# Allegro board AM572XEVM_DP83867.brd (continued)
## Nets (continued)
GND: BAT1.2(-) C2.2 C3.2 C4.2 C5.1 C6.2 C8.2 C9.2 C10.2 C12.2 C13.2 C14.2 C15.2 C16.1 C17.1 C18.1 C19.1 C20.1 C21.1 C22.1 C23.2 C24.1 C25.1 C26.1 C27.1 C28.1 C29.1 C30.2 C31.2 C32.2 C33.2 C34.2 C35.2 C36.2 C37.2 C38.2 C39.2 C40.2 C41.2 C42.2 C43.2 C44.2 C45.2 C46.2 C47.2 C48.2 C49.2 C50.2 C51.2 C52.1 C53.2 C54.2 C55.1 C56.1 C57.2 C58.1 C59.2 C60.1 C61.2 C62.1 C63.2 C64.2 C65.2 C66.1 C67.1 C68.2 C69.2 C70.2 C71.1 C72.1 C73.2 C74.2 C75.2 C76.2 C77.2 C78.1 C79.2 C80.2 C81.2 C82.2 C83.2 C84.2 C85.2 C86.2 C87.2 C88.1 C89.1 C90.2 C91.2 C92.1 C93.2 C94.2 C95.1 C96.1 C97.2 C98.1 C99.2 C104.2 C105.2 C108.2 C109.2 C110.2 C111.2 C112.2 C113.2 C114.2 C115.2 C116.2 C117.2 C118.2 C119.2 C120.2 C121.2 C122.2 C123.2 C124.2 C125.2 C126.2 C127.2 C128.2 C129.2 C130.2 C131.2 C132.2 C133.2 C134.2 C135.2 C136.2 C137.2 C138.2 C139.2 C140.2 C141.1 C142.2 C143.1 C144.2 C145.1 C146.2 C147.1 C148.2 C149.1 C150.2 C151.1 C152.2 C153.1 C154.2 C155.1 C156.2 C157.2 C158.2 C159.2 C160.2 C161.2 C162.2 C163.2 C164.2 C165.2 C166.2 C167.2 C168.2 C169.2 C170.2 C171.2 C172.2 C173.2 C174.2 C175.2 C176.2 C177.2 C178.2 C179.2 C180.2 C181.2 C182.2 C183.2 C184.2 C185.2 C186.2 C187.2 C188.2 C189.2 C190.2 C191.2 C192.2 C193.2 C194.2 C195.2 C196.2 C197.2 C198.2 C199.2 C200.2 C201.2 C202.2 C203.2 C204.2 C215.1 C216.1 C217.1 C218.1 C230.1 C231.1 C232.1 C233.1 C235.2 C236.2 C237.2 C238.2 C240.2 C243.2 C245.2 C246.2 C252.2 C253.2 C254.2 C257.2 C258.2 C259.2 C260.2 C261.2 C262.2 C263.1 C264.2 C265.2 C266.2 C267.1 C268.2 C269.2 C270.1 C271.2 C272.1 C273.2 C274.1 C275.2 C276.2 C279.2 C280.2 C283.2 C284.2 C285.2 C286.2 C287.2 C288.2 C289.2 C290.1 C291.2 C292.2 C293.2 C294.2 C295.2 C300.2 C301.2 C302.2 C303.2 C304.2 C305.2 C306.2 C307.2 C308.2 C309.2 C310.2 C311.2 C312.2 C315.2 C316.2 C317.1 C318.1 C319.2 C320.2 C321.2 C322.2 C323.2 C324.2 C325.2 C326.2 C327.2 C335.2 C336.2 C337.2 C338.2 C339.2 C340.2 C341.2 C344.2 C345.2 C346.2 C347.2 C348.2 C349.2 C350.2 C354.2 C355.2 C356.2 C357.2 C359.2 C360.2 C361.2 C363.2 C364.2 C365.2 C366.2 C367.2 C368.2 C369.2 C373.2 C374.2 C375.2 C376.2 C377.2 C378.2 C381.2 C382.2 C383.2 C384.2 C385.2 C386.2 C387.2 C389.2 C390.2 C391.2 C392.2 C393.2 C394.2 C395.2 C396.2 C397.2 C398.2 C399.2 C400.2 C402.2 C403.2 C404.2 C405.2 C406.2 C407.2 C408.2 C409.1 C410.2 C411.2 C412.2 C413.2 C414.2 C415.1 C419.2 C421.2 C428.2 C429.2 C430.2 C431.2 C432.2 C433.2 C434.2 C435.2 C436.2 C437.2 C438.2 C439.2 C440.2 C441.1 C442.2 C443.2 C445.2 C452.2 C453.2 C470.2 C471.2 C472.1 C473.1 C474.1 C475.1 C478.2 C479.2 C481.2 C482.2 C483.2 C484.2 C485.2 C486.2 C487.2 C488.2 C489.2 C490.2 C491.2 C492.2 C493.2 C494.2 C495.2 C496.2 C497.2 C498.2 C499.2 C500.1 C501.2 C510.2 C511.2 C512.2 C518.2 C519.2 C520.2 C522.2 C526.2 C527.2 C529.1 C530.1 C531.1 C532.1 C533.1 C534.1 C535.1 C536.1 C537.1 C538.1 C539.1 C540.1 C541.1 C542.1 C543.1 C544.1 C547.2 C549.2 C550.2 C551.2 C555.2 C556.2 C560.2 C561.2 C562.2 C563.2 C564.2 C565.2 C566.2 C567.2 C568.2 C569.2 C570.2 C571.2 C572.2 C573.2 C574.2 C575.2 C576.2 C577.2 C578.2 C579.2 C580.2 C583.2 C584.2 C585.2 C586.2 C587.2 C588.2 C589.2 C590.2 C591.2 C592.2 C593.2 D1.2(ANODE) D2.2(ANODE) D3.1(C) D12.2(G) D13.2(G) D14.2(G) D15.2(G) D16.2(G) D17.2(G) D18.2(G) D19.2(G) D20.4(GND) D21.4(GND) D22.4(GND) D23.4(GND) D24.2(ANODE) D25.3(GND) D26.3(GND) D27.3(GND) D28.3(GND) D29.3(GND) D30.3(GND) D31.3(GND) D32.3(GND) D33.3(GND) D34.2(GND) D35.2(GND) D36.2(GND) D37.2(GND) D38.3(GND) D40.3(GND) D41.1(C) D42.2(GND) FB9.1 J1.2 J3.3 J4.3 J6.1 L10.2 L11.2 L12.2 L21.2 L22.2 L24.2 MH5.1(TP) P1.2 P1.SHLD1 P1.SHLD2 P1.SHLD3 P1.SHLD4 P2.6 P3.6 P4.4(TDIS) P4.8(GND.1) P4.10(GND.2) P4.12(GND.3) P4.16(GND.4) P4.20(GND.5) P5.1(GND) P5.20(1_GND) P6.4(GND1) P6.5(GND2) P6.8(GND3) P6.11(GND4) P7.5(G1) P10.1 P11.2(D2 SHIELD) P11.5(D1 SHIELD) P11.8(D0 SHIELD) P11.11(CK SHIELD) P11.17(GND) P12.6(VSS) P12.10(CD2) P12.11(G1) P12.12(G2) P12.13(G3) P12.14(G4) P13.4(GND) P13.7(GNDD) P15.4(GND0) P15.7(GNDD0) P15.13(GND1) P15.16(GNDD1) P16.1 P16.2 P16.28 P16.30 P16.31 P16.32 P16.58 P16.60 P16.A2 P17.1 P17.2 P17.31 P17.32 P17.A2 P18.1 P18.2 P18.31 P18.32 P18.A2 P19.1 P19.4 P19.5 P19.9 P19.10 P19.13 P19.16 P19.19 P19.22 P19.23 P19.26 P19.29 P19.31 P19.32 P19.34 P19.37 P19.38 P19.41 P19.44 P19.47 P19.50 P19.51 P19.54 P19.57 P19.60 P19.A2 Q3.1(4) Q3.4 Q4.1(4) Q4.4 Q5.2(SOURCE) Q6.2(SOURCE) Q7.2(S) R5.1 R6.2 R11.2 R12.2 R14.1 R21.2 R22.2 R24.2 R26.2 R27.2 R28.1 R43.2 R47.2 R49.2 R50.2 R51.2 R54.1 R58.2 R66.2 R68.2 R69.1 R97.2 R98.1 R180.2 R181.2 R183.2 R188.2 R190.2 R191.2 R192.2 R193.2 R194.2 R195.2 R200.1 R203.2 R205.2 R206.1 R207.1 R209.1 R219.2 R220.2 R221.2 R222.2 R231.2 R232.2 R236.2 R244.2 R274.2 R275.2 R276.2 R277.2 R278.2 R287.1 R293.1 R296.1 R297.2 R298.2 R299.1 R300.1 R311.2 R312.2 R319.1 R323.1 R328.2 R329.1 R331.1 R332.1 R333.2 R334.2 R384.2 R385.1 R386.1 R387.1 R395.2 R397.2 R400.1 R401.1 R402.1 R403.1 R404.2 R410.2 R411.2 R416.2 R417.2 R421.2 R422.2 R432.2 R434.2 R440.1 R441.1 R478.1 S1.1(A) S2.1(A) U1.7(GND) U1.9(PAD) U2.5(GND) U2.9(PWR_PAD) U3.7(GND) U3.9(PAD) U4.2(GND) U4.4(ADD0) U5.A1(SUB_GND_A1) U5.A4(REFGND1) U5.A7(GNDANA) U5.A13(SUB_GND_A13) U5.B2(GPADC_IN0) U5.B8(SYNC_TO_EXCLOCK) U5.B10(SUB_GND_B10) U5.B11(SUB_GND_B11) U5.C2(GPADC_IN1) U5.C3(GPADC_IN2) U5.C12(SMPS12_FBK_GND) U5.D4(SMPS7_GND_1) U5.D5(SMPS7_GND_2) U5.D6(SUB_GND_D6) U5.D7(SUB_GND_D7) U5.D10(SMPS1_GND_1) U5.E4(SMPS7_GND_3) U5.E7(VAC/ACOK) U5.E8(SUB_GND_E8) U5.E9(SMPS1_GND_2) U5.E10(SMPS1_GND_3) U5.F4(SMPS4_GND_1) U5.F5(AGND.1) U5.F6(SUB_GND_F6) U5.F7(SUB_GND_F7) U5.F9(SMPS2_GND_1) U5.F10(SMPS2_GND_2) U5.G4(SMPS4_GND_2) U5.G5(SMPS4_GND_3) U5.G7(SUB_GND_G7) U5.G10(SMPS2_GND_3) U5.H4(SMPS5_GND_1) U5.H5(SMPS5_GND_2) U5.H6(SUB_GND_H6) U5.H7(SUB_GND_H7) U5.H10(SMPS3_GND_1) U5.J4(SMPS5_GND_3) U5.J6(SUB_GND_J6) U5.J9(SMPS3_GND_2) U5.J10(SMPS3_GND_3) U5.K3(SMPS45_FDBK_GND) U5.L5(SMPS6_GND) U5.L6(SMPS6_GND_1) U5.L7(SMPS9_GND) U5.L8(SMPS9_GND_1) U5.L9(SMPS8_GND_1) U5.L10(SMPS8_GND) U5.M1(SUB_GND_M1) U5.M2(SUB_GND_M2) U5.M12(GND_DIG) U5.M13(AGND.2) U5.N1(SUB_GND_N1) U5.N2(VIO_GND) U5.N13(SUB_GND_N13) U6.4(VSS) U7.14(GND.1) U7.22(GND.2) U7.33(PWR_PAD) U8.1(A0) U8.2(A1) U8.3(NC) U8.4(VSS) U9.2(GND) U10.3(GND) U11.A1(VSS.9) U11.A2(VSS.11) U11.A6(VSS.15) U11.A14(VSS.41) U11.A23(VSS.68) U11.A28(VSS.79) U11.AA8(VSS.17) U11.AA9(VSS.19) U11.AA10(VSS.14) U11.AA11(VSSA_USB.2) U11.AA14(VSS.48) U11.AA15(VSS.51) U11.AA20(VSS.61) U11.AB11(VSSA_USB.1) U11.AB14(VSS.40) U11.AB20(VSS.60) U11.AD1(VSS.3) U11.AD10(VSSA_USB3) U11.AD13(VSSA_PCIE.1) U11.AD19(VSSA_HDMI.2) U11.AD24(VSS.70) U11.AE10(VSSA_SATA) U11.AE13(VSSA_PCIE.2) U11.AE19(VSSA_HDMI.1) U11.AG1(VSS.2) U11.AH1(VSS.1) U11.AH2(VSS.10) U11.AH8(VSS.53) U11.AH20(VSS.52) U11.AH28(VSS.75) U11.B1(VSS.8) U11.D13(VSS.39) U11.D19(VSS.59) U11.E13(VSS.38) U11.E19(VSS.58) U11.F1(VSS.7) U11.F7(VSS.54) U11.G7(VSS.57) U11.G8(VSS.65) U11.G9(VSS.66) U11.H12(VSS.33) U11.J12(VSS.32) U11.J15(VSS.XX) U11.J28(VSS.78) U11.K1(VSS.6) U11.K4(VSS.12) U11.K5(VSS.13) U11.K15(VSS.28) U11.K24(VSS.55) U11.K25(VSS.56) U11.L13(VSS.37) U11.L14(VSS.46) U11.M19(VSS.69) U11.N14(VSS.X5) U11.N15(VSS.16) U11.N19(VSS.18) U11.N24(VSS.72) U11.N25(VSS.74) U11.P28(VSS.77) U11.R1(VSS.5) U11.R12(VSS.29) U11.R13(VSS.X6) U11.R15(VSS.43) U11.R21(VSS.64) U11.T10(VSS.21) U11.T11(VSS.26) U11.T12(VSS.23) U11.T14(VSS.X7) U11.T15(VSS.42) U11.T17(VSS.47) U11.T18(VSS.24) U11.T21(VSS.27) U11.U14(VSSA_VIDEO) U11.U15(VSS.X8) U11.U17(VSS.X9) U11.U20(VSS.62) U11.U21(VSS.63) U11.V15(VSS.30) U11.V17(VSS.X10) U11.W1(VSS.4) U11.W15(VSS.36) U11.W24(VSS.71) U11.W25(VSS.73) U11.W28(VSS.76) U12.2(GND) U13.2(GND) U14.49(GND) U15.49(GND) U16.6(GND) U16.11(PAD) U17.65(PAD) U18.6(DVSS) U18.21(DRVSS) U19.2(GND) U19.3(ENN) U20.1(1\O\E\) U20.4(GND) U21.5(GND1) U21.13(GND2) U21.18(GND3) U22.C4(VSSQ4) U22.E7(VSS2) U22.G5(VSS1) U22.H10(VSS3) U22.K8(VSS4) U22.N2(VSSQ1) U22.N5(VSS5) U22.P4(VSSQ3) U22.P6(VSSQ2) U23.A9(VSS.1) U23.B1(VSSQ.1) U23.B3(VSS.2) U23.B9(VSSQ.2) U23.D1(VSSQ.3) U23.D8(VSSQ.4) U23.E1(VSS.3) U23.E2(VSSQ.5) U23.E8(VSSQ.6) U23.F9(VSSQ.7) U23.G1(VSSQ.8) U23.G8(VSS.4) U23.G9(VSSQ.9) U23.J2(VSSDL) U23.J8(VSS.5) U23.M1(VSS.6) U23.M9(VSS.7) U23.P1(VSS.8) U23.P9(VSS.9) U23.T1(VSS.10) U23.T9(VSS.11) U24.A9(VSS.1) U24.B1(VSSQ.1) U24.B3(VSS.2) U24.B9(VSSQ.2) U24.D1(VSSQ.3) U24.D8(VSSQ.4) U24.E1(VSS.3) U24.E2(VSSQ.5) U24.E8(VSSQ.6) U24.F9(VSSQ.7) U24.G1(VSSQ.8) U24.G8(VSS.4) U24.G9(VSSQ.9) U24.J2(VSSDL) U24.J8(VSS.5) U24.M1(VSS.6) U24.M9(VSS.7) U24.P1(VSS.8) U24.P9(VSS.9) U24.T1(VSS.10) U24.T9(VSS.11) U25.A9(VSS.1) U25.B1(VSSQ.1) U25.B3(VSS.2) U25.B9(VSSQ.2) U25.D1(VSSQ.3) U25.D8(VSSQ.4) U25.E1(VSS.3) U25.E2(VSSQ.5) U25.E8(VSSQ.6) U25.F9(VSSQ.7) U25.G1(VSSQ.8) U25.G8(VSS.4) U25.G9(VSSQ.9) U25.J2(VSSDL) U25.J8(VSS.5) U25.M1(VSS.6) U25.M9(VSS.7) U25.P1(VSS.8) U25.P9(VSS.9) U25.T1(VSS.10) U25.T9(VSS.11) U26.A9(VSS.1) U26.B1(VSSQ.1) U26.B3(VSS.2) U26.B9(VSSQ.2) U26.D1(VSSQ.3) U26.D8(VSSQ.4) U26.E1(VSS.3) U26.E2(VSSQ.5) U26.E8(VSSQ.6) U26.F9(VSSQ.7) U26.G1(VSSQ.8) U26.G8(VSS.4) U26.G9(VSSQ.9) U26.J2(VSSDL) U26.J8(VSS.5) U26.M1(VSS.6) U26.M9(VSS.7) U26.P1(VSS.8) U26.P9(VSS.9) U26.T1(VSS.10) U26.T9(VSS.11) U27.4(PGND) U27.8(GND) U27.11(PWRPAD) U28.7(GND) U28.9(PAD) U29.1(GND) U29.11(PAD) U30.1(GND) U30.11(PAD) U31.1(GND1) U31.10(GND2) U31.12(GND3) U31.14(GND4) U31.20(GND5) U31.25(GND6) U31.27(GND7) U32.5(GND1) U32.6(GND3) U32.7(GND2) U32.8(GND4) U33.3(GND1) U33.13(GND3) U33.17(GND5) U33.18(GND4) U33.19(GND2) U33.21(PAD) U34.4(GND) U42.1(NC) U42.3(GND) U44.3(GND) U47.3(GND#3) U47.8(GND#8) U48.3(GND#3) U48.8(GND#8) U49.3(GND#3) U49.8(GND#8) U50.3(GND#3) U50.8(GND#8) U51.3(GND) Y8.1 Y8.2(NC0) Y8.4(NC1) Y9.2(NC0) Y9.4(NC1)
GND_EARTH: C215.2 C216.2 C230.2 C231.2 C415.2 C419.1 C441.2 C472.2 C473.2 C474.2 C475.2 D8.1 D9.1 D10.1 D11.1 MH1.1(TP) MH2.1(TP) MH3.1(TP) MH4.1(TP) P5.SHLD1 P5.SHLD2 P5.SHLD3 P5.SHLD4 P6.14(S1) P6.15(S2) P6.16(S3) P6.17(S4) P7.S1(G2) P7.S2(G3) P7.S3(G4) P7.S4(G5) P11.MTG1 P11.MTG2 P11.MTG3 P11.MTG4 P13.10(SHLD0) P13.11(SHLD1) P15.19(SHLD0) P15.20(SHLD1) P15.21(SHLD2) P15.22(SHLD3) R299.2 R300.2 R331.2 R332.2 R384.1 R385.2 R386.2 R387.2 R400.2 R401.2 R402.2 R403.2 S1.3(B) S1.4(BB) S2.3(B) S2.4(BB)
GND_SIGNAL: C247.2 C248.2 C249.2 FB9.2 P8.1 P9.1 R226.2 R228.2 R234.2 R235.2 U18.17(AVSS_ADC) U18.26(AVSS_DAC) U18.33(PAD)
VBUS_DET: R413.2 R414.2 U11.B11(GPIO4_21)
VCC_SENSE: R30.2 U5.B3(VCC_SENSE)
VCC_SENSE2: R29.2 U5.A11(VCC_SENSE2)
VDD_1.1: C481.1 C482.1 C483.1 C484.1 C485.1 C486.1 C487.1 C488.1 C489.1 R201.1 U16.9(OUTB) U16.10(OUTA) U17.5(VDD1) U17.8(VDD2) U17.13(VDD3) U17.21(VDD4) U17.28(VDD5) U17.31(VDD6) U17.51(VDD7) U17.57(VDD8)
VDD_1V0: C583.1 L25.2 R471.1 R473.1 TP28.1 U5.J8(SMPS9_FBK)
VDD_1V8: C47.1 C185.1 C186.1 C187.1 C188.1 C189.1 C190.1 C191.1 C192.1 C193.1 C194.1 C195.1 C196.1 L9.2 Q8.3(COLLECTOR) Q9.3(COLLECTOR) R302.2 R420.2 R425.2 TP19.1 U5.L11(SMPS8_FDBK) U11.AA7(VDDS_MLBP.1) U11.AA18(VDDS18V_DDR1.1) U11.AA19(VDDS18V_DDR1.2) U11.G18(VDDS18V.8) U11.H17(VDDS18V.11) U11.J21(VDDS18V_DDR2.3) U11.J22(VDDS18V_DDR2.4) U11.M8(VDDS18V.9) U11.M9(VDDS18V.7) U11.N8(VDDS18V.4) U11.N21(VDDS18V_DDR2.2) U11.P8(VDDS18V.5) U11.P20(VDDS18V_DDR2.5) U11.P21(VDDS18V_DDR2.1) U11.R8(VDDS18V.3) U11.T8(VDDS18V.2) U11.V21(VDDS18V.12) U11.V22(VDDS18V.6) U11.W17(VDDS18V.10) U11.W18(VDDS18V.1) U11.W21(VDDS18V_DDR1.4) U11.Y7(VDDS_MLBP.2) U11.Y21(VDDS18V_DDR1.3) U35.3(ANODE) U43.3(ANODE)
VDD_2V5: C584.1 L26.2 R472.1 R475.1 TP29.1 U5.B1(SMPS7_FDBK)
VDD_3V3: C15.1 C30.1 C50.1 C81.1 C113.1 C114.1 C115.1 C116.1 C117.1 C118.1 C119.1 C120.1 C121.1 C122.1 C123.1 C124.1 C125.1 C126.1 C127.1 C128.1 C129.1 C130.1 C131.1 C132.1 C133.1 C134.1 C135.1 C136.1 C137.1 C138.1 C139.1 C263.2 C268.1 C269.1 C271.1 C272.2 C389.1 C470.1 C471.1 C490.1 C491.1 C492.1 C493.1 C494.1 C501.1 C585.1 J3.1 J4.1 J6.3 L12.1 L22.1 L23.1 P4.5(TVD) P12.4(VDD) P16.A3 P17.A3 P18.A3 P19.A3 Q8.2(EMITTER) R8.1 R15.1 R16.1 R17.1 R18.2 R19.2 R32.1 R33.1 R37.2 R38.2 R45.1 R46.1 R48.1 R59.1 R62.1 R189.2 R196.2 R197.2 R204.2 R212.1 R213.1 R237.1 R243.1 R245.1 R246.1 R247.1 R248.1 R249.2 R286.1 R288.2 R294.1 R309.1 R310.1 R313.2 R321.1 R391.1 R392.1 R398.1 R399.1 R408.1 R415.1 R418.1 R419.1 R437.1 R470.1 R474.1 R476.1 U2.7(VOUT.2) U2.8(VOUT.1) U4.5(V+) U5.D9(VIO_IN) U6.8(VCC) U8.8(VCC) U11.AB6(VDDSHV7.1) U11.AB7(VDDSHV7.2) U11.AD5(VDDSHV6.2) U11.AD7(VDDSHV6.4) U11.AE7(VDDSHV6.3) U11.AF5(VDDSHV6.1) U11.B6(VDDSHV2.1) U11.B23(VDDSHV3.9) U11.C24(VDDSHV4.1) U11.D10(VDDSHV2.5) U11.D16(VDDSHV3.4) U11.D22(VDDSHV3.8) U11.E3(VDDSHV1.1) U11.E5(VDDSHV1.4) U11.E10(VDDSHV2.4) U11.E16(VDDSHV3.3) U11.E22(VDDSHV3.7) U11.G4(VDDSHV1.2) U11.G5(VDDSHV1.3) U11.G15(VDDSHV3.2) U11.H8(VDDSHV1.5) U11.H9(VDDSHV1.6) U11.H10(VDDSHV2.2) U11.H11(VDDSHV2.3) U11.H15(VDDSHV3.1) U11.H16(VDDSHV3.6) U11.H18(VDDSHV3.5) U11.H19(VDDSHV3.10) U11.J8(VDDSHV11.2) U11.K8(VDDSHV11.1) U11.N4(VDDSHV10.2) U11.N5(VDDSHV10.4) U11.P10(VDDSHV10.6) U11.R7(VDDSHV10.5) U11.R10(VDDSHV10.7) U11.T4(VDDSHV10.1) U11.T5(VDDSHV10.3) U11.U10(VDDSHV9.3) U11.W4(VDDSHV9.1) U11.W5(VDDSHV9.2) U16.1(INA) U16.2(INB) U16.4(BIAS) U16.5(EN) U17.16(VDD33_1) U17.34(VDD33_2) U17.52(VDD33_3) U17.63(VDD33_4) U20.7(2OE) U20.8(VCC) U21.23(VCCA) U22.C6(VCCQ4) U22.M4(VCCQ5) U22.N4(VCCQ3) U22.P5(VCCQ2) U27.10(VIN) U33.6(VCC1) U33.10(VCC4) U33.16(VCC2) U33.20(VCC3) U42.5(VCC) U44.5(VCC) U51.5(VCC)
VDD_3V3_ON: R10.2 R434.1 U2.3(ON) U5.F8(REGEN1)
VDD_3V3_SP: C94.1 C97.1 C104.1 R32.2 R41.1 R42.1 R44.1 R52.1 R405.1 U9.5(VCC) U10.5(VCC) U12.6(VDD) U34.8(VCC)
VDD_CDC: C430.1 C431.1 C433.1 L22.3 U7.1(VDD2_OUT1) U7.4(VDD1_OUT0)
VDD_CORE: C54.1 C55.2 C56.2 C58.2 C60.2 C62.2 C65.1 C66.2 C67.2 C71.2 C72.2 P3.3 R36.2 TP18.1 U5.K6(SMPS6_FBK) U11.H13(VDD.18) U11.H14(VDD.22) U11.J17(VDD.X1) U11.J18(VDD.X2) U11.L7(VDD.34) U11.L8(VDD.15) U11.N10(VDD.6) U11.N13(VDD.16) U11.P11(VDD.9) U11.P12(VDD.12) U11.P13(VDD.X3) U11.R11(VDD.8) U11.R16(VDD.26) U11.R19(VDD.27) U11.T13(VDD.13) U11.T16(VDD.25) U11.T19(VDD.X7) U11.U8(VDD.29) U11.U9(VDD.2) U11.U13(VDD.3) U11.U16(VDD.X8) U11.V8(VDD.1) U11.V16(VDD.X9)
VDD_DDR: C38.1 C156.1 C157.1 C158.1 C159.1 C160.1 C161.1 C162.1 C163.1 C164.1 C165.1 C166.1 C167.1 C168.1 C169.1 C170.1 C171.1 C172.1 C173.1 C174.1 C175.1 C176.1 C177.1 C178.1 C179.1 C180.1 C181.1 C182.1 C183.1 C184.1 C277.2 C278.2 C281.2 C282.2 C283.1 C284.1 C285.1 C286.1 C287.1 C288.1 C289.1 C290.2 C291.1 C292.1 C293.1 C294.1 C295.1 C296.2 C297.2 C298.2 C299.2 C300.1 C301.1 C302.1 C303.1 C304.1 C305.1 C306.1 C307.1 C308.1 C309.1 C310.1 C311.1 C312.1 C313.2 C314.2 C315.1 C316.1 C317.2 C318.2 C319.1 C320.1 C321.1 C322.1 C323.1 C324.1 C325.1 C326.1 C327.1 C328.2 C329.2 C330.2 C331.2 C332.2 C333.2 C334.1 C335.1 C336.1 C337.1 C338.1 C339.1 C340.1 C341.1 C342.2 C343.2 C344.1 C345.1 C346.1 C347.1 C348.1 C349.1 C350.1 C351.2 C352.2 C353.2 C354.1 C355.1 C356.1 C357.1 C358.2 C359.1 C360.1 C361.1 C362.2 C363.1 C364.1 C365.1 C366.1 C367.1 C368.1 C369.1 C370.2 C371.2 C372.2 C373.1 C374.1 C375.1 C376.1 C377.1 C378.1 C379.2 C380.2 C381.1 C382.1 C383.1 C384.1 C385.1 C386.1 C387.1 C388.1 C391.1 C392.1 C393.1 C394.1 L5.2 R273.1 R285.1 TP16.1 U5.K13(SMPS3_FDBK) U11.AA21(VDDS_DDR1.4) U11.AA22(VDDS_DDR1.2) U11.AB21(VDDS_DDR1.3) U11.AB22(VDDS_DDR1.7) U11.AB24(VDDS_DDR1.10) U11.AB25(VDDS_DDR1.11) U11.AC22(VDDS_DDR1.6) U11.AD26(VDDS_DDR1.12) U11.AG20(VDDS_DDR1.9) U11.AG28(VDDS_DDR1.5) U11.AH27(VDDS_DDR1.13) U11.E24(VDDS_DDR2.9) U11.G22(VDDS_DDR2.5) U11.G23(VDDS_DDR2.6) U11.H20(VDDS_DDR2.1) U11.H21(VDDS_DDR2.11) U11.H22(VDDS_DDR2.4) U11.J27(VDDS_DDR2.12) U11.L20(VDDS_DDR2.8) U11.L21(VDDS_DDR2.3) U11.M20(VDDS_DDR2.13) U11.M21(VDDS_DDR2.2) U11.T24(VDDS_DDR2.7) U11.T25(VDDS_DDR2.10) U11.W16(VDDS_DDR1.1) U11.W27(VDDS_DDR1.8) U23.A1(VDDQ.1) U23.A8(VDDQ.2) U23.B2(VDD.1) U23.C1(VDDQ.3) U23.C9(VDDQ.4) U23.D2(VDDQ.5) U23.D9(VDD.2) U23.E9(VDDQ.6) U23.F1(VDDQ.7) U23.G7(VDD.3) U23.H2(VDDQ.8) U23.H9(VDDQ.9) U23.K2(VDDL) U23.K8(VDD.4) U23.N1(VDD.5) U23.N9(VDD.6) U23.R1(VDD.7) U23.R9(VDD.8) U24.A1(VDDQ.1) U24.A8(VDDQ.2) U24.B2(VDD.1) U24.C1(VDDQ.3) U24.C9(VDDQ.4) U24.D2(VDDQ.5) U24.D9(VDD.2) U24.E9(VDDQ.6) U24.F1(VDDQ.7) U24.G7(VDD.3) U24.H2(VDDQ.8) U24.H9(VDDQ.9) U24.K2(VDDL) U24.K8(VDD.4) U24.N1(VDD.5) U24.N9(VDD.6) U24.R1(VDD.7) U24.R9(VDD.8) U25.A1(VDDQ.1) U25.A8(VDDQ.2) U25.B2(VDD.1) U25.C1(VDDQ.3) U25.C9(VDDQ.4) U25.D2(VDDQ.5) U25.D9(VDD.2) U25.E9(VDDQ.6) U25.F1(VDDQ.7) U25.G7(VDD.3) U25.H2(VDDQ.8) U25.H9(VDDQ.9) U25.K2(VDDL) U25.K8(VDD.4) U25.N1(VDD.5) U25.N9(VDD.6) U25.R1(VDD.7) U25.R9(VDD.8) U26.A1(VDDQ.1) U26.A8(VDDQ.2) U26.B2(VDD.1) U26.C1(VDDQ.3) U26.C9(VDDQ.4) U26.D2(VDDQ.5) U26.D9(VDD.2) U26.E9(VDDQ.6) U26.F1(VDDQ.7) U26.G7(VDD.3) U26.H2(VDDQ.8) U26.H9(VDDQ.9) U26.K2(VDDL) U26.K8(VDD.4) U26.N1(VDD.5) U26.N9(VDD.6) U26.R1(VDD.7) U26.R9(VDD.8) U27.2(VLDOIN)
VDD_DSP: C51.1 C52.2 C53.1 C57.1 C59.1 C61.1 C63.1 C64.1 C68.1 C69.1 C70.1 C73.1 C74.1 C75.1 C76.1 C78.2 C79.1 C80.1 P3.2 R35.2 TP17.1 U5.K2(SMPS45_FDBK) U11.J13(VDD_DSP.7) U11.K10(VDD_DSP.8) U11.K11(VDD_DSP.9) U11.K12(VDD_DSP.10) U11.K13(VDD_DSP.11) U11.L10(VDD_DSP.2) U11.L11(VDD_DSP.4) U11.L12(VDD_DSP.12) U11.M10(VDD_DSP.1) U11.M11(VDD_DSP.5) U11.M12(VDD_DSP.3) U11.M13(VDD_DSP.6) U11.U11(VDD_GPU.5) U11.U12(VDD_GPU.6) U11.U18(VDD_IVA.1[ECO]) U11.U19(VDD_IVA.2[ECO]) U11.V10(VDD_GPU.2) U11.V11(VDD_GPU.3) U11.V14(VDD_GPU.7) U11.V18(VDD_IVA.3[ECO]) U11.V19(VDD_IVA.4[ECO]) U11.W10(VDD_GPU.1) U11.W11(VDD_GPU.4) U11.W13(VDD_GPU.8)
VDD_MPU: C77.1 C82.1 C83.1 C84.1 C85.1 C86.1 C87.1 C88.2 C89.2 C90.1 C91.1 C92.2 C93.1 P3.5 R34.2 R54.2 TP13.1 U5.B13(SMPS12_FBK) U11.K17(VDD_MPU.10) U11.K18(VDD_MPU.2) U11.L15(VDD_MPU.11) U11.L16(VDD_MPU.12) U11.L17(VDD_MPU.6) U11.L18(VDD_MPU.8) U11.L19(VDD_MPU.3) U11.M15(VDD_MPU.13) U11.M16(VDD_MPU.14) U11.M17(VDD_MPU.5) U11.M18(VDD_MPU.7) U11.N17(VDD_MPU.4) U11.N18(VDD_MPU.1) U11.P17(VDD_MPU.15) U11.P18(VDD_MPU.9) U11.R18(VDD_MPU.16) U12.5(SENSE1)
VDD_RTC: C28.2 C108.1 U5.A5(LDO9_OUT) U11.AB15(VDD_RTC)
VDD_SD: C21.2 C140.1 D20.1(VCC) D21.1(VCC) D22.1(VCC) D23.1(VCC) R260.1 R261.1 R262.1 R263.1 R264.1 R265.1 R272.1 U5.C6(LDO1_OUT) U11.W8(VDDSHV8.2) U11.Y8(VDDSHV8.1)
VDD_SHV5: C22.2 C105.1 Q9.2(EMITTER) R423.1 R424.1 U5.B6(LDO2_OUT) U11.V12(VDDSHV5)
VDDA_1V8_PHYA: C24.2 C243.1 C245.1 L11.3 U5.K11(LDO3_OUT) U11.AA13(VDDA_USB1) U11.AB12(VDDA_USB2)
VDDA_1V8_PHYB: C500.2 L24.3 U5.K12(LDO4_OUT)
VDDA_1V8_PLL: C29.2 C99.1 L10.1 U5.B5(LDOLN_OUT) U11.AD16(VDDA_OSC.1) U11.AE16(VDDA_OSC.2)
VIN3A_CLKO: P16.50 U11.P1(VIN3X_CLKO)
VIN3A_D0: P16.51 R239.1 U11.M6(VIN3A_D0)
VIN3A_D1: P16.52 R189.1 U11.M2(VIN3A_D1)
VIN3A_D2: P16.16 R183.1 U11.L5(VIN3A_D2)
VIN3A_D3: P16.22 R188.1 U11.M1(VIN3A_D3)
VIN3A_D4: P16.15 R182.1 U11.L6(VIN3A_D4)
VIN3A_D5: P16.18 R187.1 U11.L4(VIN3A_D5)
VIN3A_D6: P16.53 R181.1 U11.L3(VIN3A_D6)
VIN3A_D7: P16.54 R180.1 U11.L2(VIN3A_D7)
VIN3A_D8: P16.23 R196.1 U11.L1(VIN3A_D8)
VIN3A_D9: P16.57 R195.1 U11.K2(VIN3A_D9)
VIN3A_D10: P16.56 R194.1 U11.J1(VIN3A_D10)
VIN3A_D11: P16.55 R193.1 U11.J2(VIN3A_D11)
VIN3A_D12: P16.24 R192.1 U11.H1(VIN3A_D12)
VIN3A_D13: P16.26 R191.1 U11.J3(VIN3A_D13)
VIN3A_D14: P16.27 R190.1 U11.H2(VIN3A_D14)
VIN3A_D15: P16.25 R197.1 R432.1 U11.H3(VIN3A_D15)
VIN3A_D16: P16.36 U11.R6(VIN3A_D16)
VIN3A_D17: P16.43 U11.T9(VIN3A_D17)
VIN3A_D18: P16.12 U11.T6(VIN3A_D18)
VIN3A_D19: P16.42 U11.T7(VIN3A_D19)
VIN3A_D20: P16.10 U11.P6(VIN3A_D20)
VIN3A_D21: P16.13 U11.R9(VIN3A_D21)
VIN3A_D22: P16.6 U11.R5(VIN3A_D22)
VIN3A_D23: P16.45 U11.P5(VIN3A_D23)
VIN3A_DEO: P16.14 U11.N9(VIN3A_DEO)
VIN3A_FLD: P16.44 U11.P9(VIN3A_FLD)
VIN3A_HSYNC: P16.9 U11.N7(VIN3A_HSYNC)
VIN3A_VSYNC: P16.37 U11.R4(VIN3A_VSYNC)
VSSA_OSC0: C100.2 C101.2 R244.1 U11.AF15(VSSA_OSC0)
VSSA_OSC1: C102.2 C103.2 R395.1 U11.AC14(VSSA_OSC1) Y3.2(NC0) Y3.4(NC1)
74801SS: R200.2 U16.7(SS)
AIC_AVDD_DAC3.3: C248.1 C249.1 L13.2 U18.25(AVDD_DAC)
AIC_BCLK: R227.2 R231.1 U18.2(BCLK)
AIC_BCLKR: R227.1 U11.B18(MCASP3_ACLKX)
AIC_DIN: R225.2 R232.1 U18.4(DIN)
AIC_DINR: R225.1 U11.B19(MCASP3_AXR0)
AIC_DOUT: R229.2 U18.5(DOUT)
AIC_DOUTR: R229.1 U11.C17(MCASP3_AXR1)
AIC_DRVDD3.3: C257.1 C258.1 C259.1 L15.2 U18.18(DRVDD#18) U18.24(DRVDD#24)
AIC_DVDD: C261.1 C262.1 U18.32(DVDD) U19.5(OUT)
AIC_IOVDD3.3: C253.1 C254.1 L14.2 U18.7(IOVDD)
AIC_MCLK: R223.2 U18.1(MCLK)
AIC_MCLKR: R223.1 U11.D18(CLKOOUT2)
AIC_WCLK: R224.2 U18.3(WCLK)
AIC_WCLKR: R224.1 U11.F15(MCASP3_FSX)
AM_CAP0: C141.2 U11.Y15(CAP_VDDRAM_CORE3)
AM_CAP1: C143.2 U11.J19(CAP_VDDRAM_CORE2)
AM_CAP2: C145.2 U11.P19(CAP_VDDRAM_CORE4)
AM_CAP3: C147.2 U11.Y16(CAP_VDDRAM_CORE5)
AM_CAP4: C149.2 U11.K9(CAP_VBBLDO_DSP)
AM_CAP5: C151.2 U11.J9(CAP_VDDRAM_DSP2)
AM_CAP6: C153.2 U11.K19(CAP_VDDRAM_MPU2)
AM_CAP7: C155.2 U11.L9(CAP_VDDRAM_CORE1)
AM_CAP8: C142.1 U11.R20(CAP_VBBLDO_IVA)
AM_CAP9: C144.1 U11.Y14(CAP_VBBLDO_GPU)
AM_CAP10: C146.1 U11.J16(CAP_VBBLDO_MPU)
AM_CAP11: C148.1 U11.J10(CAP_VDDRAM_DSP)
AM_CAP12: C150.1 U11.T20(CAP_VDDRAM_IVA)
AM_CAP13: C152.1 U11.Y13(CAP_VDDRAM_GPU)
AM_CAP14: C154.1 R417.1 U11.K16(CAP_VDDRAM_MPU1)
AUDIN_L: R230.1 U18.14(IN2L)
AUDIN_R: R233.1 U18.16(IN2R)
AUDIN_RL: C256.1 R233.2
AUDIN_RR: C255.1 R230.2
AUDIO_L: C250.1 U18.27(LEFT_LOP)
AUDIO_R: C251.1 U18.29(RIGHT_LOP)
AUXFAN_EN: R24.1 U5.A12(GPIO_2/REGEN2) U32.1(EN)
B_UART3_RX: P10.4 R236.1 U20.2(1A)
B_UART3_TX: P10.5 U20.3(2Y)
BATEN0: R204.1 U17.36(PWRON1Z_BATEN1) U29.4(EN1)
BATEN1: U17.35(PWRON2Z_BATEN2) U29.5(EN2)
BATEN2: U17.33(PWRON3Z_BATEN3) U30.4(EN1)
BATEN3: U17.32(PWRON4Z_BATEN4) U30.5(EN2)
BU_BATT: BAT1.1(+) R416.1 U6.3(VBAT)
CDC_CAP1: C436.1 U7.19(REG_CAP1)
CDC_CAP2: C437.1 U7.17(REG_CAP2)
CDC_OE: R313.1 U7.7(OE)
CDC_OS1: R310.2 R312.1 U7.10(OS1)
CDC_OS2: R309.2 R311.1 U7.11(OS0)
CDC_OSCIN: C435.1 U7.21(XIN) Y8.3
CLKOUT3: P17.41 U11.C23(CLKOUT3)
CON.PCIE_RXN0: P19.25 U11.AG13(PCIE_RXN0)
CON.PCIE_RXN1: P19.18 U11.AG11(PCIE_RXN1)
CON.PCIE_RXP0: P19.24 U11.AH13(PCIE_RXP0)
CON.PCIE_RXP1: P19.17 U11.AH11(PCIE_RXP1)
CON.PCIE_TXN0: C423.2 P19.28
CON.PCIE_TXN1: C425.2 P19.21
CON.PCIE_TXP0: C422.2 P19.27
CON.PCIE_TXP1: C424.2 P19.20
CON_MMC1_CLK: D21.3(IO1) P12.5(CLOCK) R262.2 R269.2
CON_MMC1_CMD: D21.5(IO2) P12.3(CMD) R263.2 R267.2
CON_MMC1_DAT0: D20.5(IO2) P12.7(DAT0) R261.2 R270.2
CON_MMC1_DAT1: D20.3(IO1) P12.8(DAT1) R260.2 R271.2
CON_MMC1_DAT2: D22.5(IO2) P12.1(DAT2) R265.2 R266.2
CON_MMC1_DAT3: D22.3(IO1) P12.2(CD/DAT3) R264.2 R268.2
CONN_SATA_RXN: C418.2 U33.12(RX2N)
CONN_SATA_RXP: C420.2 U33.11(RX2P)
CONN_SATA_TXN: C417.2 U33.14(TX1N)
CONN_SATA_TXP: C416.1 U33.15(TX1P)
CPU_NMIN: R46.2 R47.1 U11.D21(NMIN)
CPU_POR_RESETN: R41.2 R53.2 U9.6(C)
CPU_RESETN: R42.2 R55.1 U10.1(B)
DCAN1_RX: P17.20 U11.G19(DCAN1_RX)
DCAN1_TX: P17.50 U11.G20(DCAN1_TX)
DDR1_A0: R364.1 U11.AD20(DDR1_A0) U23.N3(A0) U24.N3(A0)
DDR1_A1: R365.1 U11.AC19(DDR1_A1) U23.P7(A1) U24.P7(A1)
DDR1_A2: R371.1 U11.AC20(DDR1_A2) U23.P3(A2) U24.P3(A2)
DDR1_A3: R376.1 U11.AB19(DDR1_A3) U23.N2(A3) U24.N2(A3)
DDR1_A4: R366.1 U11.AF21(DDR1_A4) U23.P8(A4) U24.P8(A4)
DDR1_A5: R367.1 U11.AH22(DDR1_A5) U23.P2(A5) U24.P2(A5)
DDR1_A6: R381.1 U11.AG23(DDR1_A6) U23.R8(A6) U24.R8(A6)
DDR1_A7: R369.1 U11.AE21(DDR1_A7) U23.R2(A7) U24.R2(A7)
DDR1_A8: R383.1 U11.AF22(DDR1_A8) U23.T8(A8) U24.T8(A8)
DDR1_A9: R368.1 U11.AE22(DDR1_A9) U23.R3(A9) U24.R3(A9)
DDR1_A10: R373.1 U11.AD21(DDR1_A10) U23.L7(A10) U24.L7(A10)
DDR1_A11: R380.1 U11.AD22(DDR1_A11) U23.R7(A11) U24.R7(A11)
DDR1_A12: R379.1 U11.AC21(DDR1_A12) U23.N7(A12) U24.N7(A12)
DDR1_A13: R370.1 U11.AF18(DDR1_A13) U23.T3(A13) U24.T3(A13)
DDR1_A14: R382.1 U11.AE17(DDR1_A14) U23.T7(A14) U24.T7(A14)
DDR1_A15: R375.1 U11.AD18(DDR1_A15) U23.M7(NC.M7/A15) U24.M7(NC.M7/A15)
DDR1_BA0: R363.1 U11.AF17(DDR1_BA0) U23.M2(BA0) U24.M2(BA0)
DDR1_BA1: R377.1 U11.AE18(DDR1_BA1) U23.N8(BA1) U24.N8(BA1)
DDR1_BA2: R378.1 U11.AB18(DDR1_BA2) U23.M3(BA2) U24.M3(BA2)
DDR1_CASN: R361.1 U11.AC18(DDR1_CASN) U23.K3(CAS#) U24.K3(CAS#)
DDR1_CKE: R282.1 R333.1 U11.AG22(DDR1_CKE) U23.K9(CKE) U24.K9(CKE)
DDR1_CLK0: R284.1 U11.AG24(DDR1_CK) U23.J7(CK) U24.J7(CK)
DDR1_CLK0N: R283.1 U11.AH24(DDR1_NCK) U23.K7(CK#) U24.K7(CK#)
DDR1_CLK_TERM: C388.2 R283.2 R284.2
DDR1_CSN0: R362.1 U11.AH23(DDR1_CS0N) U23.L2(CS#) U24.L2(CS#)
DDR1_D0: U11.AF25(DDR1_D0) U23.E3(DQ0)
DDR1_D1: U11.AF26(DDR1_D1) U23.H3(DQ4)
DDR1_D2: U11.AG26(DDR1_D2) U23.F8(DQ3)
DDR1_D3: U11.AH26(DDR1_D3) U23.F7(DQ1)
DDR1_D4: U11.AF24(DDR1_D4) U23.G2(DQ6)
DDR1_D5: U11.AE24(DDR1_D5) U23.H7(DQ7)
DDR1_D6: U11.AF23(DDR1_D6) U23.F2(DQ2)
DDR1_D7: U11.AE23(DDR1_D7) U23.H8(DQ5)
DDR1_D8: U11.AC23(DDR1_D8) U23.D7(DQ8)
DDR1_D9: U11.AF27(DDR1_D9) U23.C3(DQ9)
DDR1_D10: U11.AG27(DDR1_D10) U23.A3(DQ15)
DDR1_D11: U11.AF28(DDR1_D11) U23.C8(DQ10)
DDR1_D12: U11.AE26(DDR1_D12) U23.B8(DQ14)
DDR1_D13: U11.AC25(DDR1_D13) U23.A2(DQ13)
DDR1_D14: U11.AC24(DDR1_D14) U23.C2(DQ11)
DDR1_D15: U11.AD25(DDR1_D15) U23.A7(DQ12)
DDR1_D16: U11.V20(DDR1_D16) U24.E3(DQ0)
DDR1_D17: U11.W20(DDR1_D17) U24.H8(DQ5)
DDR1_D18: U11.AB28(DDR1_D18) U24.F8(DQ3)
DDR1_D19: U11.AC28(DDR1_D19) U24.H7(DQ7)
DDR1_D20: U11.AC27(DDR1_D20) U24.H3(DQ4)
DDR1_D21: U11.Y19(DDR1_D21) U24.G2(DQ6)
DDR1_D22: U11.AB27(DDR1_D22) U24.F7(DQ1)
DDR1_D23: U11.Y20(DDR1_D23) U24.F2(DQ2)
DDR1_D24: U11.AA23(DDR1_D24) U24.D7(DQ8)
DDR1_D25: U11.Y22(DDR1_D25) U24.C3(DQ9)
DDR1_D26: U11.Y23(DDR1_D26) U24.A3(DQ15)
DDR1_D27: U11.AA24(DDR1_D27) U24.B8(DQ14)
DDR1_D28: U11.Y24(DDR1_D28) U24.A7(DQ12)
DDR1_D29: U11.AA26(DDR1_D29) U24.C8(DQ10)
DDR1_D30: U11.AA25(DDR1_D30) U24.A2(DQ13)
DDR1_D31: U11.AA28(DDR1_D31) U24.C2(DQ11)
DDR1_DQM0: U11.AD23(DDR1_DQM0) U23.E7(LDM)
DDR1_DQM1: U11.AB23(DDR1_DQM1) U23.D3(UDM)
DDR1_DQM2: U11.AC26(DDR1_DQM2) U24.E7(LDM)
DDR1_DQM3: U11.AA27(DDR1_DQM3) U24.D3(UDM)
DDR1_DQS0: U11.AH25(DDR1_DQS0) U23.F3(LDQS)
DDR1_DQS1: U11.AE27(DDR1_DQS1) U23.C7(UDQS)
DDR1_DQS2: U11.AD27(DDR1_DQS2) U24.F3(LDQS)
DDR1_DQS3: U11.Y28(DDR1_DQS3) U24.C7(UDQS)
DDR1_DQS_ECC: R274.1 U11.V27(DDR1_DQS_ECC)
DDR1_DQSN0: U11.AG25(DDR1_DQSN0) U23.G3(LDQS#)
DDR1_DQSN1: U11.AE28(DDR1_DQSN1) U23.B7(UDQS#)
DDR1_DQSN2: U11.AD28(DDR1_DQSN2) U24.G3(LDQS#)
DDR1_DQSN3: U11.Y27(DDR1_DQSN3) U24.B7(UDQS#)
DDR1_DQSN_ECC: R273.2 U11.V28(DDR1_DQSN_ECC)
DDR1_ODT0: R360.1 U11.AE20(DDR1_ODT0) U23.K1(ODT) U24.K1(ODT)
DDR1_RASN: R372.1 U11.AF20(DDR1_RASN) U23.J3(RAS#) U24.J3(RAS#)
DDR1_RST: TP20.1 U11.AG21(DDR1_RST) U23.T2(RSTN) U24.T2(RSTN)
DDR1_WEN: R374.1 U11.AH21(DDR1_WEN) U23.L3(WE#) U24.L3(WE#)
DDR2_A0: R355.1 U11.R25(DDR2_A0) U25.N3(A0) U26.N3(A0)
DDR2_A1: R356.1 U11.R26(DDR2_A1) U25.P7(A1) U26.P7(A1)
DDR2_A2: R346.1 U11.R28(DDR2_A2) U25.P3(A2) U26.P3(A2)
DDR2_A3: R344.1 U11.R27(DDR2_A3) U25.N2(A3) U26.N2(A3)
DDR2_A4: R347.1 U11.P23(DDR2_A4) U25.P8(A4) U26.P8(A4)
DDR2_A5: R345.1 U11.P22(DDR2_A5) U25.P2(A5) U26.P2(A5)
DDR2_A6: R338.1 U11.P25(DDR2_A6) U25.R8(A6) U26.R8(A6)
DDR2_A7: R358.1 U11.N20(DDR2_A7) U25.R2(A7) U26.R2(A7)
DDR2_A8: R359.1 U11.P27(DDR2_A8) U25.T8(A8) U26.T8(A8)
DDR2_A9: R336.1 U11.N27(DDR2_A9) U25.R3(A9) U26.R3(A9)
DDR2_A10: R340.1 U11.N23(DDR2_A10) U25.L7(A10) U26.L7(A10)
DDR2_A11: R337.1 U11.P26(DDR2_A11) U25.R7(A11) U26.R7(A11)
DDR2_A12: R354.1 U11.N28(DDR2_A12) U25.N7(A12) U26.N7(A12)
DDR2_A13: R357.1 U11.T22(DDR2_A13) U25.T3(A13) U26.T3(A13)
DDR2_A14: R339.1 U11.R22(DDR2_A14) U25.T7(A14) U26.T7(A14)
DDR2_A15: R342.1 U11.U22(DDR2_A15) U25.M7(NC.M7/A15) U26.M7(NC.M7/A15)
DDR2_BA0: R350.1 U11.U23(DDR2_BA0) U25.M2(BA0) U26.M2(BA0)
DDR2_BA1: R353.1 U11.U27(DDR2_BA1) U25.N8(BA1) U26.N8(BA1)
DDR2_BA2: R352.1 U11.U26(DDR2_BA2) U25.M3(BA2) U26.M3(BA2)
DDR2_CASN: R349.1 U11.U28(DDR2_CASN) U25.K3(CAS#) U26.K3(CAS#)
DDR2_CKE: R334.1 R348.1 U11.U24(DDR2_CKE) U25.K9(CKE) U26.K9(CKE)
DDR2_CLK0: R281.1 U11.T28(DDR2_CK) U25.J7(CK) U26.J7(CK)
DDR2_CLK0N: R280.1 U11.T27(DDR2_NCK) U25.K7(CK#) U26.K7(CK#)
DDR2_CLK_TRM: C334.2 R280.2 R281.2
DDR2_CSN0: R351.1 U11.P24(DDR2_CSN0) U25.L2(CS#) U26.L2(CS#)
DDR2_D0: U11.E26(DDR2_D0) U25.D7(DQ8)
DDR2_D1: U11.G25(DDR2_D1) U25.C2(DQ11)
DDR2_D2: U11.F25(DDR2_D2) U25.A3(DQ15)
DDR2_D3: U11.F24(DDR2_D3) U25.B8(DQ14)
DDR2_D4: U11.F26(DDR2_D4) U25.A2(DQ13)
DDR2_D5: U11.F27(DDR2_D5) U25.C3(DQ9)
DDR2_D6: U11.E27(DDR2_D6) U25.A7(DQ12)
DDR2_D7: U11.E28(DDR2_D7) U25.C8(DQ10)
DDR2_D8: U11.H23(DDR2_D8) U25.E3(DQ0)
DDR2_D9: U11.H25(DDR2_D9) U25.H3(DQ4)
DDR2_D10: U11.H24(DDR2_D10) U25.H8(DQ5)
DDR2_D11: U11.H26(DDR2_D11) U25.G2(DQ6)
DDR2_D12: U11.G26(DDR2_D12) U25.H7(DQ7)
DDR2_D13: U11.J25(DDR2_D13) U25.F2(DQ2)
DDR2_D14: U11.J26(DDR2_D14) U25.F8(DQ3)
DDR2_D15: U11.J24(DDR2_D15) U25.F7(DQ1)
DDR2_D16: U11.L22(DDR2_D16) U26.D7(DQ8)
DDR2_D17: U11.K20(DDR2_D17) U26.C8(DQ10)
DDR2_D18: U11.K21(DDR2_D18) U26.A2(DQ13)
DDR2_D19: U11.L23(DDR2_D19) U26.C2(DQ11)
DDR2_D20: U11.L24(DDR2_D20) U26.C3(DQ9)
DDR2_D21: U11.J23(DDR2_D21) U26.B8(DQ14)
DDR2_D22: U11.K22(DDR2_D22) U26.A3(DQ15)
DDR2_D23: U11.J20(DDR2_D23) U26.A7(DQ12)
DDR2_D24: U11.L27(DDR2_D24) U26.E3(DQ0)
DDR2_D25: U11.L26(DDR2_D25) U26.H8(DQ5)
DDR2_D26: U11.L25(DDR2_D26) U26.H7(DQ7)
DDR2_D27: U11.L28(DDR2_D27) U26.F7(DQ1)
DDR2_D28: U11.M23(DDR2_D28) U26.F8(DQ3)
DDR2_D29: U11.M24(DDR2_D29) U26.H3(DQ4)
DDR2_D30: U11.M25(DDR2_D30) U26.F2(DQ2)
DDR2_D31: U11.M26(DDR2_D31) U26.G2(DQ6)
DDR2_DQM0: U11.F28(DDR2_DQM0) U25.D3(UDM)
DDR2_DQM1: U11.G24(DDR2_DQM1) U25.E7(LDM)
DDR2_DQM2: U11.K23(DDR2_DQM2) U26.D3(UDM)
DDR2_DQM3: U11.M22(DDR2_DQM3) U26.E7(LDM)
DDR2_DQS0: U11.G28(DDR2_DQS0) U25.C7(UDQS)
DDR2_DQS1: U11.H27(DDR2_DQS1) U25.F3(LDQS)
DDR2_DQS2: U11.K27(DDR2_DQS2) U26.C7(UDQS)
DDR2_DQS3: U11.M28(DDR2_DQS3) U26.F3(LDQS)
DDR2_DQSN0: U11.G27(DDR2_DQSN0) U25.B7(UDQS#)
DDR2_DQSN1: U11.H28(DDR2_DQSN1) U25.G3(LDQS#)
DDR2_DQSN2: U11.K28(DDR2_DQSN2) U26.B7(UDQS#)
DDR2_DQSN3: U11.M27(DDR2_DQSN3) U26.G3(LDQS#)
DDR2_ODT0: R341.1 U11.R23(DDR2_ODT0) U25.K1(ODT) U26.K1(ODT)
DDR2_RASN: R279.1 U11.T23(DDR2_RASN) U25.J3(RAS#) U26.J3(RAS#)
DDR2_RST: TP21.1 U11.R24(DDR2_RST) U25.T2(RSTN) U26.T2(RSTN)
DDR2_WEN: R343.1 U11.U25(DDR2_WEN) U25.L3(WE#) U26.L3(WE#)
DDR_REFIN: C390.1 R285.2 R287.2 U27.1(REFIN)
DDR_VREF_OFFN: Q5.1(GATE) R288.1 U11.A22(GPIO7_11) U27.7(EN)
DDR_VREFSTL1: C273.1 C275.1 C276.1 C277.1 C278.1 R290.2 U11.Y18(DDR1_VREF0) U23.H1(VREFDQ) U23.M8(VREFCA) U24.H1(VREFDQ) U24.M8(VREFCA)
DDR_VREFSTL2: C274.2 C279.1 C280.1 C281.1 C282.1 R291.2 U11.N22(DDR2_VREF0) U25.H1(VREFDQ) U25.M8(VREFCA) U26.H1(VREFDQ) U26.M8(VREFCA)
DMA_EVT1: P16.35 U11.P7(DMA_EVT1)
DMA_EVT3: P16.11 U11.N6(DMA_EVT3)
DMA_EVT4: P16.17 U11.M4(DMA_EVT4)
EEWP: R37.1 TP4.1(TP) U8.7(WP)
EHRPWM2_TRIPZONE_INPUT: P18.6 U11.F6(EHRPWM2_TRIPZONE_INPUT)
EHRPWM2A: P17.5 U11.AC5(EHRPWM2A)
EHRPWM2B: P18.44 U11.D3(EHRPWM2B)
EMAC[0]_RXC: U11.U5(EMAC(0)_RXC) U14.32(RX_CLK)
EMAC[0]_RXCTL: U11.V5(EMAC(0)_RXCTL) U14.38(RX_DV/RX_CTRL)
EMAC[0]_RXD0: U11.W2(EMAC(0)_RXD0) U14.33(RX_D0)
EMAC[0]_RXD1: U11.Y2(EMAC(0)_RXD1) U14.34(RX_D1)
EMAC[0]_RXD2: U11.V3(EMAC(0)_RXD2) U14.35(RX_D2)
EMAC[0]_RXD3: U11.V4(EMAC(0)_RXD3) U14.36(RX_D3)
EMAC[0]_TXC: R85.1 U11.W9(EMAC(0)_TXC)
EMAC[0]_TXCTL: R84.1 U11.V9(EMAC(0)_TXCTL)
EMAC[0]_TXD0: R86.1 U11.U6(EMAC(0)_TXD0)
EMAC[0]_TXD1: R87.1 U11.V6(EMAC(0)_TXD1)
EMAC[0]_TXD2: R88.1 U11.U7(EMAC(0)_TXD2)
EMAC[0]_TXD3: R89.1 U11.V7(EMAC(0)_TXD3)
EMAC[1]_RXC: U11.C5(EMAC(1)_RXC) U15.32(RX_CLK)
EMAC[1]_RXCTL: U11.A3(EMAC(1)_RXCTL) U15.38(RX_DV/RX_CTRL)
EMAC[1]_RXD0: R461.2 U11.A4(EMAC(1)_RXD0) U15.33(RX_D0)
EMAC[1]_RXD1: U11.B5(EMAC(1)_RXD1) U15.34(RX_D1)
EMAC[1]_RXD2: U11.B4(EMAC(1)_RXD2) U15.35(RX_D2)
EMAC[1]_RXD3: U11.B3(EMAC(1)_RXD3) U15.36(RX_D3)
EMAC[1]_TXC: R112.1 U11.D5(EMAC(1)_TXC)
EMAC[1]_TXCTL: R111.1 U11.C2(EMAC(1)_TXCTL)
EMAC[1]_TXD0: R113.1 U11.D6(EMAC(1)_TXD0)
EMAC[1]_TXD1: R114.1 U11.B2(EMAC(1)_TXD1)
EMAC[1]_TXD2: R115.1 U11.C4(EMAC(1)_TXD2)
EMAC[1]_TXD3: R118.1 U11.C3(EMAC(1)_TXD3)
EMMC_VDD1.1: C270.2 U22.C2(VCCI)
EMU0: P4.13(EMU0) R59.2 U11.G21(EMU0)
EMU1: P4.14(EMU1) R62.2 U11.D24(EMU1)
EMU_RSTN: P4.15(SRST) R44.2 U10.2(A)
ENET0_INTN: R468.2 U11.D26(GPIO7_27) U14.44(INT/PWDN)
ENET1_INTN: R469.2 U11.D28(GPIO7_26) U15.44(INT/PWDN)
ENET_PORZ: R39.2 R40.2 U44.2(B) U51.2(B)
ESATA_R+: C420.1 P6.10(B+)
ESATA_R-: C418.1 P6.9(B-)
ESATA_T+: C416.2 P6.6(A+)
ESATA_T-: C417.1 P6.7(A-)
ETH0_1V0: C518.1 C519.1 C520.1 C522.1 C566.1 C567.1 C568.1 C569.1 R471.2 U14.6(VDD1P0#6) U14.24(VDD1P0#24) U14.31(VDD1P0#31) U14.42(VDD1P0#42)
ETH0_2V5: C526.1 C527.1 C570.1 C571.1 R472.2 U14.3(VDDA2P5#3) U14.9(VDDA2P5#9)
ETH0_3V3: C510.1 C511.1 C512.1 C563.1 C564.1 C565.1 R442.1 R468.1 R470.2 U14.19(VDDIO#19) U14.30(VDDIO#30) U14.41(VDDIO#41)
ETH0_LED0_YEL_LINK: P5.27(LED1_A) U14.47(LED_0)
ETH0_LED2_GRN_ACTIV: P5.29(LED2_A) U14.45(LED_2)
ETH0_RBIAS: R440.2 U14.12(RBIAS)
ETH0_RESET: U14.43(RESET_N) U51.4(Y)
ETH0_TRCT[0]: C590.1 P5.14(1_TRCT1)
ETH0_TRCT[1]: C591.1 P5.22(1_TRCT2)
ETH0_TRCT[2]: C592.1 P5.17(1_TRCT3)
ETH0_TRCT[3]: C593.1 P5.25(1_TRCT4)
ETH0_TRD[0]N: C530.2 P5.21(1_TRD1_N) U14.2(TD_M_A) U47.2(D1-) U47.9(NC9)
ETH0_TRD[0]P: C529.2 P5.15(1_TRD1_P) U14.1(TD_P_A) U47.1(D1+) U47.10(NC10)
ETH0_TRD[1]N: C531.2 P5.16(1_TRD2_N) U14.5(TD_M_B) U47.5(D2-) U47.6(NC6)
ETH0_TRD[1]P: C532.2 P5.23(1_TRD2_P) U14.4(TD_P_B) U47.4(D2+) U47.7(NC7)
ETH0_TRD[2]N: C533.2 P5.24(1_TRD3_N) U14.8(TD_M_C) U48.2(D1-) U48.9(NC9)
ETH0_TRD[2]P: C534.2 P5.18(1_TRD3_P) U14.7(TD_P_C) U48.1(D1+) U48.10(NC10)
ETH0_TRD[3]N: C535.2 P5.19(1_TRD4_N) U14.11(TD_M_D) U48.5(D2-) U48.6(NC6)
ETH0_TRD[3]P: C536.2 P5.26(1_TRD4_P) U14.10(TD_P_D) U48.4(D2+) U48.7(NC7)
ETH0_XI: C217.2 U14.15(XI) Y5.2(NC0)
ETH0_XO: C218.2 R479.1 Y5.1
ETH1_1V0: C547.1 C549.1 C550.1 C551.1 C575.1 C576.1 C577.1 C578.1 R473.2 U15.6(VDD1P0#6) U15.24(VDD1P0#24) U15.31(VDD1P0#31) U15.42(VDD1P0#42)
ETH1_2V5: C555.1 C556.1 C579.1 C580.1 R475.2 U15.3(VDDA2P5#3) U15.9(VDDA2P5#9)
ETH1_3V3: C560.1 C561.1 C562.1 C572.1 C573.1 C574.1 R461.1 R469.1 R474.2 U15.19(VDDIO#19) U15.30(VDDIO#30) U15.41(VDDIO#41)
ETH1_LED0_YEL_LINK: P5.31(LED3_A) U15.47(LED_0)
ETH1_LED2_GRN_ACTIV: P5.33(LED4_A) U15.45(LED_2)
ETH1_RBIAS: R441.2 U15.12(RBIAS)
ETH1_RESET: U15.43(RESET_N) U44.4(Y)
ETH1_TRCT[0]: C586.1 P5.7(2_TRCT1)
ETH1_TRCT[1]: C587.1 P5.12(2_TRCT2)
ETH1_TRCT[2]: C588.1 P5.4(2_TRCT3)
ETH1_TRCT[3]: C589.1 P5.9(2_TRCT4)
ETH1_TRD[0]N: C537.2 P5.13(2_TRD1_N) U15.2(TD_M_A) U49.2(D1-) U49.9(NC9)
ETH1_TRD[0]P: C544.2 P5.6(2_TRD1_P) U15.1(TD_P_A) U49.1(D1+) U49.10(NC10)
ETH1_TRD[1]N: C538.2 P5.5(2_TRD2_N) U15.5(TD_M_B) U49.5(D2-) U49.6(NC6)
ETH1_TRD[1]P: C539.2 P5.11(2_TRD2_P) U15.4(TD_P_B) U49.4(D2+) U49.7(NC7)
ETH1_TRD[2]N: C540.2 P5.10(2_TRD3_N) U15.8(TD_M_C) U50.2(D1-) U50.9(NC9)
ETH1_TRD[2]P: C541.2 P5.3(2_TRD3_P) U15.7(TD_P_C) U50.1(D1+) U50.10(NC10)
ETH1_TRD[3]N: C542.2 P5.2(2_TRD4_N) U15.11(TD_M_D) U50.5(D2-) U50.6(NC6)
ETH1_TRD[3]P: C543.2 P5.8(2_TRD4_P) U15.10(TD_P_D) U50.4(D2+) U50.7(NC7)
ETH1_XI: C232.2 R451.2 U15.15(XI) Y6.2(NC0)
ETH1_XO: C233.2 R480.1 Y6.1
ETH_CLK_OUT: R451.1 R477.1
ETH_RESETN: R476.2 U11.U3(GPIO3_17) U51.1(A)
EXP_SATA_RXN: P19.7 U31.22(B1-)
EXP_SATA_RXP: P19.8 U31.21(B1+)
EXP_SATA_TXN: P19.36 U31.23(B0-)
EXP_SATA_TXP: P19.35 U31.24(B0+)
EXT_WAKE: P18.35 R33.2 R49.1 U6.7(MFP) U11.AC16(WAKEUP3)
GPIO2_2: P16.46 U11.P4(GPIO2_2)
GPIO2_3: P16.7 U11.R3(GPIO2_3)
GPIO2_4: P16.40 U11.T2(GPIO2_4)
GPIO2_5: P16.38 U11.U2(GPIO2_5)
GPIO2_6: P16.39 U11.U1(GPIO2_6)
GPIO2_8: P16.8 U11.R2(GPIO2_8)
GPIO2_17: P16.48 U11.P3(GPIO2_17)
GPIO2_19: P16.41 U11.T1(GPIO2_19)
GPIO2_20: P16.49 U11.P2(GPIO2_20)
GPIO2_23: P16.21 U11.N1(GPIO2_23)
GPIO2_24: P16.47 U11.M5(GPIO2_24)
GPIO2_25: P16.19 U11.M3(GPIO2_25)
GPIO2_28: P16.20 U11.N2(GPIO2_28)
GPIO2_31: P19.55 U11.AH7(GPIO2_31)
GPIO3_6: P19.56 U11.AG7(GPIO3_6)
GPIO3_7: P19.52 U11.AH6(GPIO3_7)
GPIO3_8: P19.45 U11.AH3(GPIO3_8)
GPIO3_9: P19.48 U11.AH5(GPIO3_9)
GPIO3_10: P19.53 U11.AG6(GPIO3_10)
GPIO3_11: P19.14 U11.AH4(GPIO3_11)
GPIO3_12: P19.15 U11.AG4(GPIO3_12)
GPIO3_14: P19.46 U11.AG3(GPIO3_14)
GPIO3_15: P19.49 U11.AG5(GPIO3_15)
GPIO3_16: P19.42 U11.AF2(GPIO3_16)
GPIO3_18: P19.43 U11.AF3(GPIO3_18)
GPIO3_20: P19.11 U11.AF1(GPIO3_20)
GPIO3_23: P19.39 U11.AE1(GPIO3_23)
GPIO3_24: P19.12 U11.AE2(GPIO3_24)
GPIO3_26: P19.40 U11.AD2(GPIO3_26)
GPIO3_28: P18.11 U11.E1(GPIO3_28)
GPIO3_29: R437.2 U11.G2(GPIO3_29) U44.1(A)
GPIO3_30: P18.36 U11.H7(GPIO3_30)
GPIO4_7: P18.43 U11.C1(GPIO4_7)
GPIO4_8: P18.39 U11.E4(GPIO4_8)
GPIO4_9: P18.38 U11.F5(GPIO4_9)
GPIO4_10: P18.7 U11.E6(GPIO4_10)
GPIO4_17: P16.3 U11.A12(GPIO4_17)
GPIO5_4: P17.47 U11.G13(GPIO5_4)
GPIO5_5: P17.17 U11.J11(GPIO5_5)
GPIO5_6: P17.45 U11.E12(GPIO5_6)
GPIO5_7: P17.15 U11.F13(GPIO5_7)
GPIO5_8: P17.55 U11.C12(GPIO5_8)
GPIO5_9: P17.25 U11.D12(GPIO5_9)
GPIO5_10: P16.34 U11.B12(GPIO5_10)
GPIO5_11: P16.4 U11.A11(GPIO5_11)
GPIO5_12: P16.33 U11.B13(GPIO5_12)
GPIO5_18: P18.59 U11.V2(UART3_RXD)
GPIO5_19: P18.29 U11.Y1(UART3_TXD)
GPIO6_11: P17.3 U11.AB4(GPIO6_11)
GPIO6_18: P17.58 U11.E17(GPIO6_18)
GPIO6_19: P17.28 U11.B26(GPIO6_19)
GPIO7_7: P17.51 U11.A25(GPIO7_7)
GRSTZ: C246.1 U17.50(GRSTZ)
HDMI1_DDC_SCL: R246.2 U11.C25(HDMI1_DDC_SCL) U21.1(SCL_A)
HDMI1_DDC_SDA: R245.2 U11.F17(HDMI1_DDC_SDA) U21.2(SDA_A)
HDMI_5VOUT: C265.1 P11.18(+5V) U21.12(5V_OUT)
HDMI_CEC_A: U11.B20(HDMI_CEC) U21.24(CEC_A)
HDMI_CEC_B: P11.13(CE REMOTE) R237.2 U21.6(CEC_B)
HDMI_CT_HPD: R248.2 U11.A24(GPIO7_10) U21.11(CT_HPD)
HDMI_HPD_A: U11.B21(HDMI_HPD) U21.3(HPD_A)
HDMI_HPD_B: P11.19(HP DET) U21.9(HPD_B)
HDMI_LS_OE: R247.2 U11.AG8(GPIO2_30) U21.4(LS_OE)
HDMI_SCL_B: P11.15(DDC CLK) R241.2 U21.7(SCL_B)
HDMI_SDA_B: P11.16(DDC DATA) R242.1 U21.8(SDA_B)
HDMI_TX0+: D16.1(I) FL3.3 P11.7(D0+)
HDMI_TX0-: D17.1(I) FL3.2 P11.9(D0-)
HDMI_TX1+: D14.1(I) FL2.3 P11.4(D1+)
HDMI_TX1-: D15.1(I) FL2.2 P11.6(D1-)
HDMI_TX2+: D12.1(I) FL1.3 P11.1(D2+)
HDMI_TX2-: D13.1(I) FL1.2 P11.3(D2-)
HDMI_TXC+: D18.1(I) FL4.3 P11.10(CK+)
HDMI_TXC-: D19.1(I) FL4.2 P11.12(CK-)
HUB_XI: C235.1 R202.1 U17.62(XI) Y7.1
HUB_XO: C240.1 R202.2 U17.61(XO) Y7.2
I2C1_SCL: R17.2 R212.2 U4.1(SCL) U5.L1(I2C1_SCL_SCK) U8.6(SCL) U11.C20(I2C1_SCL) U18.8(SCL)
I2C1_SDA: R16.2 R213.2 U4.6(SDA) U5.L2(I2C1_SDA_SDI) U8.5(SDA) U11.C21(I2C1_SDA) U18.9(SDA)
I2C3_SCL: R392.2 R393.1 U6.6(SCL) U11.D14(I2C3_SCL)
I2C3_SDA: R391.2 R394.1 U6.5(SDA) U11.C14(I2C3_SDA)
I2C4_SCL: P17.46 U11.J14(I2C4_SCL)
I2C4_SDA: P17.53 U11.B14(I2C4_SDA)
I2C5_SCL: P18.4 U11.F12(I2C5_SCL)
I2C5_SDA: P18.3 U11.G12(I2C5_SDA)
LDO_VRTC: C19.2 C110.1 J5.2 R20.2 R23.1 R56.1 R214.2 R433.2 U5.A8(LDOVRTC_OUT) U11.AB13(VDDA_RTC)
LEDAA: D4.2(A) R215.2
LEDAC: D4.1(C) Q3.6(3)
LEDBA: D5.2(A) R216.2
LEDBC: D5.1(C) Q3.3
LEDCA: D6.2(A) R217.2
LEDCC: D6.1(C) Q4.6(3)
LEDDA: D7.2(A) R218.2
LEDDC: D7.1(C) Q4.3
LEFT_IN: C255.2 D10.2 P9.2 R235.1
LEFT_OUT: C250.2 D8.2 P8.2 R226.1
MCASP2_ACLKR: P17.44 U11.E15(MCASP2_ACLKR)
MCASP2_AXR0: P17.54 U11.B15(MCASP2_AXR0)
MCASP2_AXR1: P17.23 U11.A15(MCASP2_AXR1)
MCASP2_AXR2: P17.18 U11.C15(MCASP2_AXR2)
MCASP2_AXR3: P17.22 U11.A16(MCASP2_AXR3)
MCASP2_AXR4: P17.16 U11.D15(MCASP2_AXR4)
MCASP2_AXR5: P17.24 U11.B16(MCASP2_AXR5)
MCASP2_AXR6: P17.26 U11.B17(MCASP2_AXR6)
MCASP2_AXR7: P17.56 U11.A17(MCASP2_AXR7)
MCASP2_CLKX: P17.21 U11.A19(MCASP2_ACLKX)
MCASP2_FSR: P17.57 U11.A20(MCASP2_FSR)
MCASP2_FSX: P17.52 U11.A18(MCASP2_FSX)
MCASP7_AXR0: P16.5 U11.E14(MCASP7_AXR0)
MCASP7_AXR1: P17.49 U11.A13(MCASP7_AXR1)
MCASP7_CLKX: P17.48 U11.G14(MCASP7_CLKX)
MCASP7_FSX: P17.19 U11.F14(MCASP7_FSX)
MDIO_CLK: U11.V1(MDIO_MCLK) U14.16(MDC) U15.16(MDC)
MDIO_DATA: R442.2 U11.U4(MDIO_DATA) U14.17(MDIO) U15.17(MDIO)
MMC1_CLK: R269.1 U11.W6(MMC1_CLK)
MMC1_CMD: R267.1 U11.Y6(MMC1_CMD)
MMC1_DAT0: R270.1 U11.AA6(MMC1_DAT0)
MMC1_DAT1: R271.1 U11.Y4(MMC1_DAT1)
MMC1_DAT2: R266.1 U11.AA5(MMC1_DAT2)
MMC1_DAT3: R268.1 U11.Y3(MMC1_DAT3)
MMC1_SD_CD: D23.5(IO2) P12.9(CD1) R272.2 U11.W7(MMC1_SDCD)
MMC2_3V3: C266.1 C267.2 R249.1 R250.1 R251.1 R252.1 R253.1 R254.1 R255.1 R256.1 R257.1 R258.1 R259.1 U22.E6(VCC3) U22.F5(VCC2) U22.J10(VCC0) U22.K9(VCC1) U22.P3(VCCQ1)
MMC2_CLK: R250.2 U11.J7(MMC2_CLK) U22.M6(CLK)
MMC2_CMD: R251.2 U11.H6(MMC2_CMD) U22.M5(CMD)
MMC2_DAT0: R252.2 U11.J4(MMC2_DAT0) U22.A3(DAT0)
MMC2_DAT1: R253.2 U11.J6(MMC2_DAT1) U22.A4(DAT1)
MMC2_DAT2: R254.2 U11.H4(MMC2_DAT2) U22.A5(DAT2)
MMC2_DAT3: R255.2 U11.H5(MMC2_DAT3) U22.B2(DAT3)
MMC2_DAT4: R256.2 U11.K7(MMC2_DAT4) U22.B3(DAT4)
MMC2_DAT5: R257.2 U11.M7(MMC2_DAT5) U22.B4(DAT5)
MMC2_DAT6: R258.2 U11.J5(MMC2_DAT6) U22.B5(DAT6)
MMC2_DAT7: R259.2 U11.K6(MMC2_DAT7) U22.B6(DAT7)
MMC3_CLK: P17.34 U11.AD4(MMC3_CLK)
MMC3_CMD: P17.4 U11.AC4(MMC3_CMD)
MMC3_DAT0: P17.7 U11.AC7(MMC3_DAT0)
MMC3_DAT1: P17.36 U11.AC6(MMC3_DAT1)
MMC3_DAT2: P17.8 U11.AC9(MMC3_DAT2)
MMC3_DAT3: P17.33 U11.AC3(MMC3_DAT3)
MMC3_DAT4: P17.37 U11.AC8(MMC3_DAT4)
MMC3_DAT5: P17.35 U11.AD6(MMC3_DAT5)
MMC3_DAT6: P17.38 U11.AB8(MMC3_DAT6)
MMC3_DAT7: P17.6 U11.AB5(MMC3_DAT7)
OC0: U17.46(OVERCUR1Z) U29.10(F\A\U\L\T\1\)
OC1: U17.47(OVERCUR2Z) U29.6(F\A\U\L\T\2\)
OC2: U17.44(OVERCUR3Z) U30.10(F\A\U\L\T\1\)
OC3: U17.43(OVERCUR0Z) U30.6(F\A\U\L\T\2\)
OSC0_XI: C101.1 U11.AE15(XI_OSC0) Y2.1
OSC0_XO: C100.1 U11.AD15(X0_OSC0) Y2.2(NC0)
OSC1_XI: C103.1 U11.AC15(XI_OSC1) Y3.1
OSC1_XO: C102.1 U11.AC13(XO_OSC1) Y3.3
PCI_CONN_REFN: P19.58 U7.2(OUT1N)
PCI_CONN_REFP: P19.59 U7.3(OUT1P)
PCIE_TXN0: C423.1 U11.AG14(PCIE_TXN0)
PCIE_TXN1: C425.1 U11.AG12(PCIE_TXN1)
PCIE_TXP0: C422.1 U11.AH14(PCIE_TXP0)
PCIE_TXP1: C424.1 U11.AH12(PCIE_TXP1)
PMIC_BOOT0: R20.1 R21.1 U5.L3(BOOT0)
PMIC_BOOT1: R22.1 R214.1 U5.K7(BOOT1)
PMIC_GPIO_0: R421.1 U5.B12(GPIO_0)
PMIC_GPIO_3: R26.1 U5.H9(GPIO_3)
PMIC_GPIO_5: R27.1 U5.C10(GPIO_5/CLK32KGO)
PMIC_INT: R48.2 U5.K1(INT) U11.AD17(WAKEUP0)
PMIC_OFF: R45.2 R322.1 U11.Y11(ON_OFF)
PMIC_POWERGOOD: TP5.1 U5.J7(POWERGOOD)
PMIC_POWERHOLD: J5.1 R23.2 R28.2 U5.G9(GPIO_7/POWERHOLD)
PMIC_RESET_IN: R56.2 U5.K9(RESET_IN) U13.1(R\E\S\E\T)
PMIC_RESET_OUT: U5.G6(RESET_OUT) U9.1(A)
PMIC_SCE: R19.1 U5.M3(I2C2_SCL_SCE)
PMIC_SDO: R18.1 U5.H8(I2C2_SDA_SDO)
PMIC_VBUS_DET: R414.1 U5.C13(GPIO_1/VBUSDET)
PMIC_XTAL_IN: C452.1 U5.A3(OSC16MIN) Y9.3
PMIC_XTAL_OUT: C453.1 U5.A2(OSC16MOUT) Y9.1
POR_CT: C109.1 U12.4(CT)
PORZ: C95.2 C96.2 R39.1 R57.1 U9.4(Y) U11.AB17(RTC_PORZ) U11.F22(PORZ)
PR1_UART0_CTSN: P18.40 U11.G1(PR1_UART0_CTSN)
PR1_UART0_RTSN: P18.37 U11.G6(PR1_UART0_RTSN)
PR1_UART0_RXD: P18.41 U11.F2(PR1_UART0_RXD)
PR1_UART0_TXD: P18.10 U11.F3(PR1_UART0_TXD)
PS_3V3: C23.1 C26.2 C27.2 C33.1 C35.1 C37.1 C39.1 C41.1 C43.1 C45.1 C46.1 C48.1 C111.1 C442.1 P3.1 R7.2 R10.1 R13.1 R29.1 R30.1 R58.1 R335.1 R407.1 U2.1(VIN.1) U2.2(VIN.2) U5.C4(LDO9_IN) U5.C5(LDOLN_IN) U5.C7(VCC1) U5.D11(SMPS1_IN_1) U5.D12(SMPS1_IN_2) U5.D13(SMPS1_IN_3) U5.E1(SMPS7_IN_B1_1) U5.E2(SMPS7_IN_B1_2) U5.E3(SMPS7_IN_B1_3) U5.F1(SMPS4_IN_1) U5.F2(SMPS4_IN_2) U5.F3(SMPS4_IN_3) U5.G11(SMPS2_IN_1) U5.G12(SMPS2_IN_2) U5.G13(SMPS2_IN_3) U5.H11(SMPS3_IN_1) U5.H12(SMPS3_IN_2) U5.H13(SMPS3_IN_3) U5.J1(SMPS5_IN_1) U5.J2(SMPS5_IN_2) U5.J3(SMPS5_IN_3) U5.L12(LDO34_IN) U5.L13(LDO34_IN_1) U5.M4(NC6) U5.M6(SMPS6_IN) U5.M8(SMPS9_IN) U5.M9(SMPS8_IN) U5.N3(NC7) U5.N4(NC8) U5.N6(SMPS6_IN_1) U5.N8(SMPS9_IN_1) U5.N9(SMPS8_IN_1) U13.5(SENSE1) U13.6(VDD)
PS_3V3_COMP: C11.1 C12.1 U3.6(COMP)
PS_3V3_EN: R9.2 R11.1 U3.3(EN)
PS_3V3_SNS: R13.2 R14.2 U3.5(VSNS)
PS_3V3_SS: C13.1 U3.4(SS)
PS_3V3_TAP: C8.1 C9.1 L2.2 P2.1 R7.1
PUSB_RXN0: C242.1 U11.AF12(USB_RXN0)
PUSB_RXP0: C241.1 U11.AE12(USB_RXP0)
PUSB_TXN0: C244.1 U11.AC11(USB_TXN0)
PUSB_TXP0: C239.1 U11.AD11(USB_TXP0)
PWRON: C478.1 P18.5 R407.2 S1.2(AA) U5.G8(PWRON)
R_3V3LED: D3.2(A) R8.2
R_12VLED: D41.2(A) R240.2
R_EMAC[0]_TXC: R85.2 U14.29(GTX_CLK)
R_EMAC[0]_TXCTL: R84.2 U14.37(TX_EN/TX_CTRL)
R_EMAC[0]_TXD0: R86.2 U14.28(TX_D0)
R_EMAC[0]_TXD1: R87.2 U14.27(TX_D1)
R_EMAC[0]_TXD2: R88.2 U14.26(TX_D2)
R_EMAC[0]_TXD3: R89.2 U14.25(TX_D3)
R_EMAC[1]_TXC: R112.2 U15.29(GTX_CLK)
R_EMAC[1]_TXCTL: R111.2 U15.37(TX_EN/TX_CTRL)
R_EMAC[1]_TXD0: R113.2 U15.28(TX_D0)
R_EMAC[1]_TXD1: R114.2 U15.27(TX_D1)
R_EMAC[1]_TXD2: R115.2 U15.26(TX_D2)
R_EMAC[1]_TXD3: R118.2 U15.25(TX_D3)
RDRXN: C456.2 U33.4(TX2N)
RDRXP: C455.2 U33.5(TX2P)
RDTXN: C457.2 U33.2(RX1N)
RDTXP: C454.1 U33.1(RX1P)
RESETIN: P18.34 R52.2 S2.2(AA) U12.3(M\R\)
RHDMI_TX0+: FL3.4 U11.AH17(HDMI1_DATA0Y)
RHDMI_TX0-: FL3.1 U11.AG17(HDMI1_DATA0X)
RHDMI_TX1+: FL2.4 U11.AH18(HDMI1_DATA1Y)
RHDMI_TX1-: FL2.1 U11.AG18(HDMI1_DATA1X)
RHDMI_TX2+: FL1.4 U11.AH19(HDMI1_DATA2Y)
RHDMI_TX2-: FL1.1 U11.AG19(HDMI1_DATA2X)
RHDMI_TXC+: FL4.4 U11.AH16(HDMI1_CLOCKY)
RHDMI_TXC-: FL4.1 U11.AG16(HDMI1_CLOCKX)
RIGHT_IN: C256.2 D11.2 P9.3 R234.1
RIGHT_OUT: C251.2 D9.2 P8.3 R228.1
RSTOUTN: P18.33 R38.1 R40.1 R43.1 R318.1 U7.12(RSTN) U11.F23(RSTOUTN) U18.31(RESETN) U22.K5(R\S\T\) U34.2(2B)
RTC_ISO: R57.2 U11.AF14(RTC_ISO)
RTC_X1: C32.1 U6.1(X1) Y1.2
RTC_X2: C31.1 U6.2(X2) Y1.1
RTCK: P4.9(TCKRTN) R63.2
RTCKR: R63.1 U11.E18(RTCK)
RXN_MUXC: C456.1 U31.16(C1-)
RXP_MUXC: C455.1 U31.15(C1+)
SAT_RXN: U11.AH9(SATA1_RXN0) U31.6(A1-)
SAT_RXP: U11.AG9(SATA1_RXP0) U31.7(A1+)
SAT_TXN: U11.AG10(SATA1_TXN0) U31.5(A0-)
SAT_TXP: U11.AH10(SATA1_TXP0) U31.4(A0+)
SATA_SEL: P19.6 R303.2 U31.3(SEL)
SCL_HUB: R393.2 U17.38(SCL_SMBCLK)
SDA_HUB: R394.2 U17.37(SDA_SMBDAT)
SERDES_CLKN: C426.2 R308.1 U11.AH15(LJCB_CLKN)
SERDES_CLKP: C427.2 R308.2 U11.AG15(LJCB_CLKP)
SERDES_IN_REFN: C426.1 U7.5(OUT0N)
SERDES_IN_REFP: C427.1 U7.6(OUT0P)
SMPS6: C44.1 L8.2 P2.3 R36.1
SMPS_1_2: C34.1 C36.1 L3.2 L4.2 P2.5 R34.1
SMPS_4/5: C40.1 C42.1 L6.2 L7.2 P2.2 R35.1
SS_SUSPEND: R243.2 U17.45(HS_SUSPEND)
SW1: L3.1 U5.E11(SMPS1_SW_1) U5.E12(SMPS1_SW_2) U5.E13(SMPS1_SW_3)
SW2: L4.1 U5.F11(SMPS2_SW_1) U5.F12(SMPS2_SW_2) U5.F13(SMPS2_SW_3)
SW3: L5.1 U5.J11(SMPS3_SW_1) U5.J12(SMPS3_SW_2) U5.J13(SMPS3_SW_3)
SW4: L6.1 U5.G1(SMPS4_SW_1) U5.G2(SMPS4_SW_2) U5.G3(SMPS4_SW_3)
SW5: L7.1 U5.H1(SMPS5_SW_1) U5.H2(SMPS5_SW_2) U5.H3(SMPS5_SW_3)
SW6: L8.1 U5.M5(SMPS6_SW_1) U5.N5(SMPS6_SW)
SW7: L26.1 U5.D1(SMPS7_SW_1) U5.D2(SMPS7_SW_2) U5.D3(SMPS7_SW_3)
SW8: L9.1 U5.M10(SMPS8_SW) U5.N10(SMPS8_SW_1)
SW9: L25.1 U5.M7(SMPS9_SW) U5.N7(SMPS9_SW_1)
TCK: R64.1 U11.E20(TCLK)
TCLK: P4.11(TCLK) R64.2
TDI: P4.3(TDI) U11.D23(TDI)
TDO: P4.7(TDO) R61.2
TDOR: R61.1 U11.F19(TDO)
TESTV: TP9.1 U5.N12(VPROG/TESTV)
TIMER1: P17.42 U11.E21(TIMER1)
TIMER2: P17.13 U11.F20(TIMER2)
TIMER3: P17.12 U11.F21(TIMER3)
TMP102_ALERT: R15.2 U4.3(ALERT) U11.G17(GPIO7_16)
TMS: P4.1(TMS) U11.F18(TMS)
TPS_ENABLE1: TP7.1 U5.J5(ENABLE1)
TPS_PWRDOWN: TP8.1 U5.K8(PWRDOWN)
TPS_RST: R53.1 R55.2 U12.1(R\E\S\E\T)
TRSTN: P4.2(TRSTN) R66.1 U11.D20(TRSTN)
TX1+: C449.2 D29.1(D+) P15.9(TX0+)
TX1-: C448.2 D29.2(D-) P15.8(TX0-)
TX2+: C451.2 D31.1(D+) P15.18(TX1+)
TX2-: C450.2 D31.2(D-) P15.17(TX1-)
TX+: C447.2 D26.1(D+) P13.9(TX+)
TX-: C446.2 D26.2(D-) P13.8(TX-)
TXN_MUXC: C457.1 U31.17(C0-)
TXP_MUXC: C454.2 U31.18(C0+)
U1-1: C1.2 U1.1(BOOT)
U1-3: R3.2 R6.1 U1.3(EN)
U1-4: C4.1 U1.4(SS)
U1-8: C1.1 D1.1(CATHODE) L1.1 U1.8(PH)
U2-6: C10.1 U2.6(CT)
U3-1: C7.2 U3.1(BOOT)
U3-8: C7.1 D2.1(CATHODE) L2.1 U3.8(PH)
U5_C8: C25.2 U5.C8(LDOVANA_OUT)
U13-4: C112.1 U13.4(CT)
U16_FB: R201.2 R203.1 U16.8(FB)
U17_A17: R207.2 U17.40(FULLPWRMGMTZ_SMBA1)
U17_A41: R209.2 U17.42(GANGED/SMBA2/HS_UP)
U28_1: C401.2 U28.1(BOOT)
U28_3: R294.2 R297.1 U28.3(EN)
U28_4: C408.1 U28.4(SS)
U28_6: C409.2 R295.1 U28.6(COMP)
U28_8: C401.1 D24.1(CATHODE) L16.1 U28.8(PH)
U28_RC: C410.1 R295.2
U29_7: R293.2 U29.7(ILIM)
U30_7: R298.1 U30.7(ILIM)
U31_1V8: C421.1 L21.1 R303.1 U31.9(VDD1) U31.11(VDD2) U31.13(VDD3) U31.19(VDD4) U31.26(VDD5) U31.28(VDD6)
U31_VDD: L21.3 R302.1
U32_ADJ: C443.1 R396.2 R397.1 U32.4(ADJ)
UART1_RXD: P18.60 U11.C26(UART1_TXD)
UART1_TXD: P18.30 U11.B27(UART1_RXD)
UART3_RXD: U11.D27(GPIO1_16) U20.6(1Y)
UART3_TXD: U11.C28(GPIO1_17) U20.5(2A)
UART8_CTSN: P17.11 U11.G16(UART8_CTSN)
UART8_RTSN: P17.14 U11.D17(UART8_RTSN)
UART8_RXD: P17.43 U11.C18(UART8_RXD)
UART8_TXD: P17.27 U11.A21(UART8_TXD)
UART9_CTSN: P17.40 U11.AB3(UART9_CTSN)
UART9_RTSN: P17.39 U11.AA4(UART9_RTSN)
UART9_RXD: P17.10 U11.AA3(UART9_RXD)
UART9_TXD: P17.9 U11.AB9(UART9_TXD)
UART10_CTSN: P18.13 U11.D2(UART10_CTSN)
UART10_RTSN: P18.8 U11.F4(UART10_RTSN)
UART10_RXD: P18.12 U11.D1(UART10_RXD)
UART10_TXD: P18.42 U11.E2(UART10_TXD)
USB1_DM: U11.AC12(USB1_DM) U17.54(USB_DM_UP)
USB1_DP: U11.AD12(USB1_DP) U17.53(USB_DP_UP)
USB1_DRVBUS_R: R330.1 U11.AB10(USB1_DRVVBUS)
USB1_DRVVBUS: R329.2 R330.2 U17.48(USB_VBUS)
USB1_ID: R205.1 U11.C27(GPIO7_25)
USB1V: C404.1 C405.1 L18.1 U29.9(OUT1)
USB1VBUS: D35.1(IO) L18.2 P13.1(USBVDD)
USB2_5V: C479.1 D42.1(IO) P7.1(VB) R31.1 R320.1 R412.1
USB2_DM: R211.1 R315.1 U11.AF11(USB2_DM)
USB2_DMEX: P16.29 R315.2
USB2_DP: R210.1 R314.1 U11.AE11(USB2_DP)
USB2_DPEX: P16.59 R314.2
USB2_DRVBUS: P17.59 U11.AC10(USB2_DRVVBUS)
USB2_ID: P17.30 R321.2 U11.E25(GPIO7_24)
USB2_OC: P17.29 U11.B24(GPIO7_17)
USB2_VBUS: R411.1 R412.2 U5.D8(VBUS)
USB2V: C406.1 C407.1 L17.1 U29.8(OUT2)
USB2VBUS: D34.1(IO) L17.2 P15.1(VBUS0)
USB2VBUS_EXP: P17.60 R320.2
USB3V: C411.1 C412.1 L19.1 U30.9(OUT1)
USB3VBUS: D36.1(IO) L19.2 P15.10(VBUS1)
USB4V: C413.1 C414.1 L20.1 U30.8(OUT2)
USB4VBUS: D37.1(IO) L20.2 P6.1(VBUS0)
USB_5V: C403.1 L16.2 R292.1 U29.2(IN1) U29.3(IN2) U30.2(IN1) U30.3(IN2)
USB_DM0: D27.1(D+) P13.2(D-) U17.2(USB_DM_DN1)
USB_DM1: D30.2(D-) P15.2(D0-) U17.10(USB_DM_DN2)
USB_DM2: D33.2(D-) P15.11(D1-) U17.18(USB_DM_DN3)
USB_DM3: D32.2(D-) P6.2(D-) U17.25(USB_DM_DN4)
USB_DP0: D27.2(D-) P13.3(D+) U17.1(USB_DP_DN1)
USB_DP1: D30.1(D+) P15.3(D0+) U17.9(USB_DP_DN2)
USB_DP2: D33.1(D+) P15.12(D1+) U17.17(USB_DP_DN3)
USB_DP3: D32.1(D+) P6.3(D+) U17.24(USB_DP_DN4)
USB_R1: R206.2 U17.64(USB_R1)
USB_RXM0: D25.2(D-) P13.5(RX-) U17.7(USB_SSRXM_DN1)
USB_RXM1: D28.2(D-) P15.5(RX0-) U17.15(USB_SSRXM_DN2)
USB_RXM2: D38.2(D-) P15.14(RX1-) U17.23(USB_SSRXM_DN3)
USB_RXP0: D25.1(D+) P13.6(RX+) U17.6(USB_SSRXP_DN1)
USB_RXP1: D28.1(D+) P15.6(RX0+) U17.14(USB_SSRXP_DN2)
USB_RXP2: D38.1(D+) P15.15(RX1+) U17.22(USB_SSRXP_DN3)
USB_SNS: R292.2 R296.2 U28.5(VSNS)
USB_SSRXM0: C244.2 U17.59(USB_SSRXM_UP)
USB_SSRXP0: C239.2 U17.58(USB_SSRXP_UP)
USB_SSTXM0: C242.2 U17.56(USB_SSTXM_UP)
USB_SSTXP0: C241.2 U17.55(USB_SSTXP_UP)
USB_TXM0: C446.1 U17.4(USB_SSTXM_DN1)
USB_TXM1: C448.1 U17.12(USB_SSTXM_DN2)
USB_TXM2: C450.1 U17.20(USB_SSTXM_DN3)
USB_TXP0: C447.1 U17.3(USB_SSTXP_DN1)
USB_TXP1: C449.1 U17.11(USB_SSTXP_DN2)
USB_TXP2: C451.1 U17.19(USB_SSTXP_DN3)
USBSP_DM: D40.2(D-) P7.2(D-) R211.2
USBSP_DP: D40.1(D+) P7.3(D+) R210.2
USR0: Q3.2(5) R219.1 U11.F16(GPIO7_8)
USR1: Q3.5 R220.1 U11.B25(GPIO7_9)
USR2: Q4.2(5) R221.1 U11.A26(GPIO7_14)
USR3: Q4.5 R222.1 U11.B22(GPIO7_15)
VBG: C16.2 U5.B7(VBG)
VDAC_3V3: C247.1 C252.1 C260.1 L12.3 L13.1 L14.1 L15.1 U19.1(IN)
VOUT1_CLK: P18.57 R149.2
VOUT1_D0: P18.25 R124.2
VOUT1_D1: P18.55 R125.2
VOUT1_D2: P18.54 R126.2
VOUT1_D3: P18.26 R127.2
VOUT1_D4: P18.48 R128.2
VOUT1_D5: P18.49 R129.2
VOUT1_D6: P18.45 R130.2
VOUT1_D7: P18.46 R131.2
VOUT1_D8: P18.47 R132.2
VOUT1_D9: P18.56 R133.2
VOUT1_D10: P18.16 R134.2
VOUT1_D11: P18.18 R135.2
